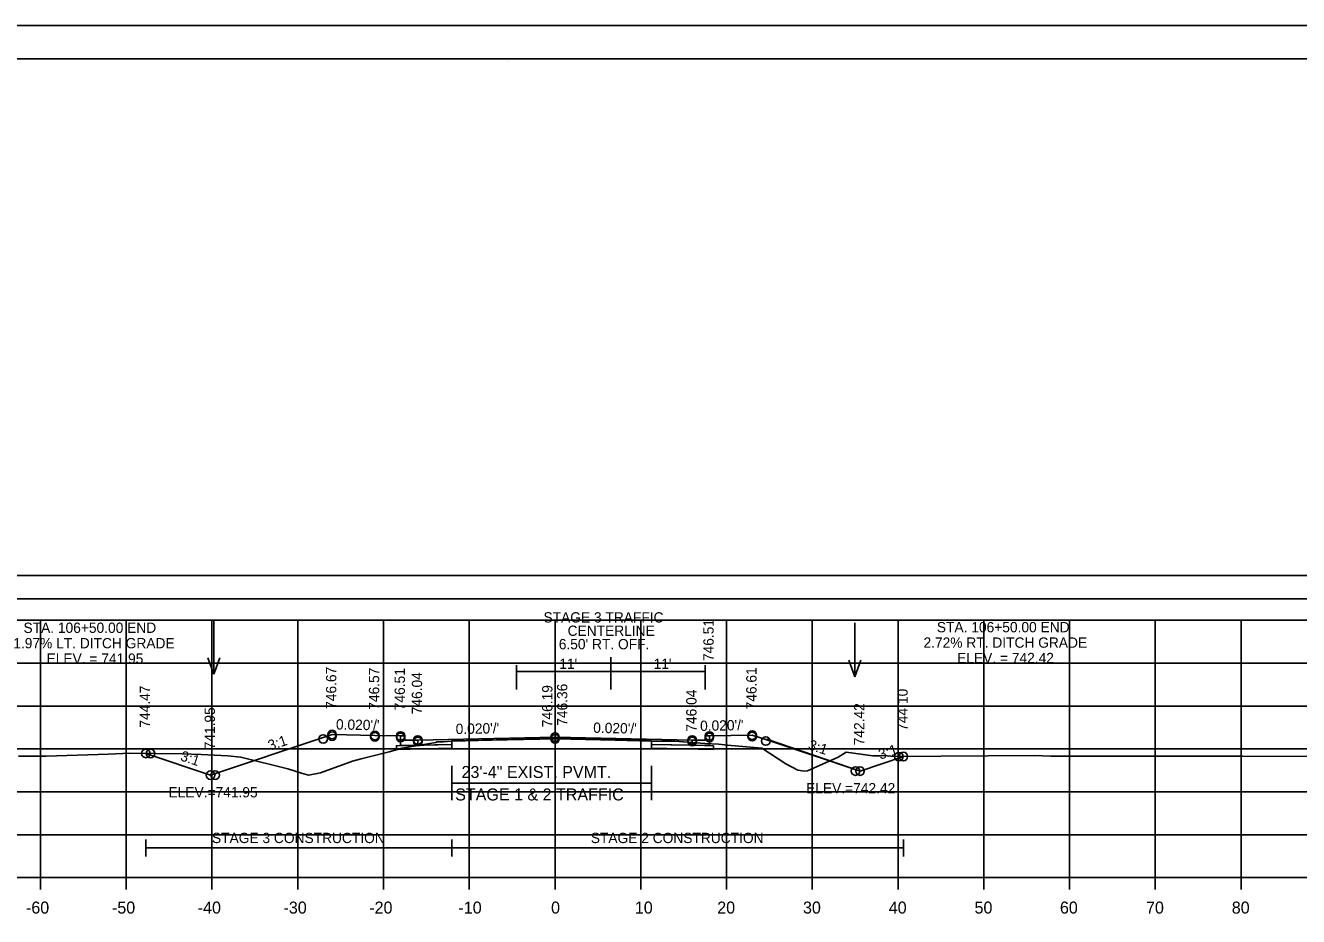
# Model space of a CAD drawing. Extents: x 1202951 to 1376887, y 378065 to 728038.
# Drawn here: x 1376522.9 to 1376671.4, y 379797.3 to 379901.2 of the extents above; entities that cross this region are included whole.
import ezdxf

# ---------------------------------------------------------------- set-up
doc = ezdxf.new("R2010")
doc.units = 0
for name, color, linetype in [('Default', 7, 'Continuous'), ('R_Alt Surface', 7, 'Continuous'), ('R_Axis', 7, 'Continuous'), ('R_Axis Annot', 7, 'Continuous'), ('R_Border', 7, 'Continuous'), ('R_Border Notes', 7, 'Continuous'), ('R_Dimension', 7, 'Continuous'), ('R_Exist Surface', 7, 'Continuous'), ('R_Fin Surface', 7, 'Continuous'), ('R_Grid', 7, 'Continuous'), ('R_MOT', 7, 'Continuous'), ('R_No Plot', 7, 'Continuous'), ('R_Proposed Const Limits', 7, 'Continuous'), ('R_Water Annot', 7, 'Continuous'), ('R_Xsect Elev', 7, 'Continuous'), ('R_Xsect Slope', 7, 'Continuous')]:
    doc.layers.add(name, color=color, linetype=linetype)

msp = doc.modelspace()

# ---------------------------------------------------------------- linework, layer by layer
at = {"layer": 'Default'}
for points in [[(1376558.67, 379818.51), (1376557.64, 379818.17), (1376557.64, 379818.17), (1376544.51, 379813.79)], [(1376607.67, 379818.45), (1376609.25, 379817.93), (1376609.25, 379817.93), (1376620.24, 379814.26)]]:
    msp.add_lwpolyline(points, dxfattribs=at)
for points in [[(1376566.67, 379818.35), (1376567.16, 379818.35), (1376567.17, 379817.85), (1376568.67, 379817.88), (1376568.67, 379817.26), (1376566.67, 379817.22)], [(1376602.67, 379818.35), (1376602.18, 379818.35), (1376602.17, 379817.85), (1376600.67, 379817.88), (1376600.67, 379817.26), (1376602.67, 379817.22)]]:
    msp.add_lwpolyline(points, close=True, dxfattribs=at)
at = {"layer": 'R_Alt Surface'}
for p, q in [((1376572.63, 379817.34), (1376566.17, 379817.21)), ((1376595.92, 379817.35), (1376602.67, 379817.22))]:
    msp.add_line(p, q, dxfattribs=at)
for points in [[(1376434.67, 379834.34), (1376710.2, 379834.34), (1376710.2, 379837.05), (1376434.67, 379837.05)], [(1376568.67, 379817.26), (1376567.17, 379817.23), (1376566.17, 379817.21), (1376566.17, 379816.79), (1376572.63, 379816.92), (1376572.63, 379817.34)], [(1376568.67, 379817.88), (1376568.67, 379817.26), (1376572.63, 379817.34), (1376572.63, 379817.8), (1376584.67, 379818.04), (1376595.92, 379817.81), (1376595.92, 379817.35), (1376600.67, 379817.26), (1376600.67, 379817.88), (1376600.67, 379817.88), (1376584.67, 379818.2), (1376568.67, 379817.88)], [(1376603.17, 379817.21), (1376602.1, 379817.23), (1376600.67, 379817.26), (1376595.92, 379817.35), (1376595.92, 379816.93), (1376603.17, 379816.79)]]:
    msp.add_lwpolyline(points, close=True, dxfattribs=at)
msp.add_lwpolyline([(1376566.67, 379818.35), (1376566.67, 379817.22), (1376568.67, 379817.26), (1376572.63, 379817.34), (1376572.63, 379817.8), (1376584.67, 379818.04), (1376595.92, 379817.81), (1376595.92, 379817.35), (1376600.67, 379817.26), (1376602.67, 379817.22), (1376602.67, 379818.35)], dxfattribs=at)
at = {"layer": 'R_Axis'}
for p, q in [((1376434.67, 379801.84), (1376734.67, 379801.84)), ((1376524.67, 379800.44), (1376524.67, 379801.84)), ((1376534.67, 379800.44), (1376534.67, 379801.84)), ((1376544.67, 379800.44), (1376544.67, 379801.84)), ((1376554.67, 379800.44), (1376554.67, 379801.84)), ((1376564.67, 379800.44), (1376564.67, 379801.84)), ((1376574.67, 379800.44), (1376574.67, 379801.84)), ((1376584.67, 379800.44), (1376584.67, 379801.84)), ((1376594.67, 379800.44), (1376594.67, 379801.84)), ((1376604.67, 379800.44), (1376604.67, 379801.84)), ((1376614.67, 379800.44), (1376614.67, 379801.84)), ((1376624.67, 379800.44), (1376624.67, 379801.84)), ((1376634.67, 379800.44), (1376634.67, 379801.84)), ((1376644.67, 379800.44), (1376644.67, 379801.84)), ((1376654.67, 379800.44), (1376654.67, 379801.84)), ((1376664.67, 379800.44), (1376664.67, 379801.84))]:
    msp.add_line(p, q, dxfattribs=at)
at = {"layer": 'R_Border'}
for p, q in [((1376426.67, 379897.3), (1376742.85, 379897.3)), ((1376579.19, 379897.04), (1376579.19, 379897.04)), ((1376579.19, 379897.04), (1376579.19, 379897.04))]:
    msp.add_line(p, q, dxfattribs=at)
at = {"layer": 'R_Dimension'}
for points in [[(1376536.95, 379806.29), (1376536.95, 379804.29)], [(1376536.95, 379805.29), (1376572.63, 379805.29)], [(1376572.63, 379806.29), (1376572.63, 379804.29)], [(1376572.63, 379805.29), (1376625.29, 379805.29)], [(1376625.29, 379806.29), (1376625.29, 379804.29)]]:
    msp.add_lwpolyline(points, dxfattribs=at)
at = {"layer": 'R_Exist Surface'}
msp.add_lwpolyline([(1376522.1, 379815.98), (1376522.99, 379815.98), (1376525.35, 379816.01), (1376532.6, 379816.24), (1376535.09, 379816.34), (1376541.19, 379816.26), (1376543.4, 379816.18), (1376546.52, 379816.03), (1376548.04, 379815.88), (1376553.5, 379814.51), (1376555.11, 379814), (1376555.94, 379813.79), (1376557.31, 379814.04), (1376561.04, 379815.43), (1376562.06, 379815.69), (1376565.35, 379816.5), (1376566.84, 379816.93), (1376569.15, 379817.33), (1376570.78, 379817.6), (1376570.89, 379817.65), (1376571.66, 379817.66), (1376572.63, 379817.75), (1376577.26, 379817.85), (1376584.77, 379818.03), (1376591.67, 379817.85), (1376595.92, 379817.76), (1376596.82, 379817.73), (1376598.64, 379817.73), (1376602.15, 379817.49), (1376603.73, 379817.38), (1376604.8, 379817.28), (1376608.78, 379816.93), (1376611.6, 379815.1), (1376612.97, 379814.35), (1376613.78, 379814.26), (1376614.12, 379814.29), (1376617.7, 379815.86), (1376618.61, 379816.45), (1376621.72, 379816.03), (1376622.58, 379816.04), (1376623.02, 379816.07), (1376624.23, 379815.94), (1376640.57, 379816.06), (1376641.53, 379816.03), (1376642.48, 379816.01), (1376661.53, 379816), (1376661.67, 379816), (1376664.85, 379816), (1376680.87, 379815.96)], dxfattribs=at)
at = {"layer": 'R_Fin Surface'}
for p, q in [((1376572.63, 379814.85), (1376572.63, 379810.85)), ((1376595.92, 379814.85), (1376595.92, 379810.85)), ((1376572.63, 379812.85), (1376595.92, 379812.85))]:
    msp.add_line(p, q, dxfattribs=at)
for points in [[(1376536.95, 379816.32), (1376544.51, 379813.79), (1376557.64, 379818.17), (1376558.67, 379818.51), (1376563.67, 379818.41), (1376566.67, 379818.35), (1376567.16, 379818.35), (1376567.17, 379817.85), (1376568.67, 379817.88), (1376584.67, 379818.2), (1376600.67, 379817.88), (1376602.17, 379817.85), (1376602.18, 379818.35), (1376602.67, 379818.35), (1376607.67, 379818.45), (1376609.25, 379817.93), (1376609.5, 379817.93), (1376620.24, 379814.26), (1376625.29, 379815.95)], [(1376558.67, 379818.51), (1376563.67, 379818.41), (1376566.67, 379818.35), (1376567.16, 379818.35), (1376567.17, 379817.85), (1376568.67, 379817.88), (1376568.67, 379817.88), (1376584.67, 379818.2), (1376600.67, 379817.88), (1376600.67, 379817.88), (1376602.17, 379817.85), (1376602.18, 379818.35), (1376602.67, 379818.35), (1376602.67, 379818.35), (1376607.67, 379818.45)]]:
    msp.add_lwpolyline(points, dxfattribs=at)
at = {"layer": 'R_Grid'}
for p, q in [((1376434.67, 379831.84), (1376734.67, 379831.84)), ((1376524.67, 379801.84), (1376524.67, 379831.84)), ((1376534.67, 379801.84), (1376534.67, 379831.84)), ((1376544.67, 379801.84), (1376544.67, 379831.84)), ((1376554.67, 379801.84), (1376554.67, 379831.84)), ((1376564.67, 379801.84), (1376564.67, 379831.84)), ((1376574.67, 379801.84), (1376574.67, 379831.84)), ((1376584.67, 379801.84), (1376584.67, 379831.84)), ((1376594.67, 379801.84), (1376594.67, 379831.84)), ((1376604.67, 379801.84), (1376604.67, 379831.84)), ((1376614.67, 379801.84), (1376614.67, 379831.84)), ((1376624.67, 379801.84), (1376624.67, 379831.84)), ((1376634.67, 379801.84), (1376634.67, 379831.84)), ((1376644.67, 379801.84), (1376644.67, 379831.84)), ((1376654.67, 379801.84), (1376654.67, 379831.84)), ((1376664.67, 379801.84), (1376664.67, 379831.84)), ((1376434.67, 379826.84), (1376734.67, 379826.84)), ((1376434.67, 379821.84), (1376734.67, 379821.84)), ((1376434.67, 379816.84), (1376734.67, 379816.84)), ((1376434.67, 379811.84), (1376734.67, 379811.84)), ((1376434.67, 379806.84), (1376734.67, 379806.84)), ((1376434.67, 379801.84), (1376734.67, 379801.84))]:
    msp.add_line(p, q, dxfattribs=at)
at = {"layer": 'R_MOT'}
for p, q in [((1376591.18, 379827.53), (1376591.18, 379823.77)), ((1376580.18, 379826.62), (1376580.18, 379823.77)), ((1376580.18, 379825.87), (1376591.18, 379825.87)), ((1376591.18, 379825.87), (1376602.18, 379825.87)), ((1376602.18, 379826.62), (1376602.18, 379823.77))]:
    msp.add_line(p, q, dxfattribs=at)
at = {"layer": 'R_No Plot'}
msp.add_line((1376414.27, 379901.2), (1376747.6, 379901.2), dxfattribs=at)
for points in [[(1376414.27, 380114.54), (1376747.61, 380114.54), (1376747.61, 379901.2), (1376414.27, 379901.2)], [(1376414.26, 379901.2), (1376747.6, 379901.2), (1376747.6, 379687.86), (1376414.26, 379687.86)], [(1376660.59, 379897.3), (1376680.21, 379897.3), (1376680.21, 379887.42), (1376696.32, 379887.42), (1376719.52, 379887.42), (1376719.64, 379859.27), (1376742.85, 379859.27), (1376742.85, 379691.84), (1376426.67, 379691.84), (1376426.67, 379897.3)]]:
    msp.add_lwpolyline(points, close=True, dxfattribs=at)
for centre in [(1376557.64, 379818), (1376558.67, 379818.51), (1376558.67, 379818.34), (1376563.67, 379818.41), (1376563.67, 379818.24), (1376566.67, 379818.35), (1376566.67, 379818.18), (1376568.67, 379817.88), (1376584.67, 379818.2), (1376584.67, 379818.03), (1376600.67, 379817.88), (1376602.67, 379818.35), (1376602.67, 379818.35), (1376602.67, 379818.18), (1376602.67, 379818.18), (1376607.67, 379818.45), (1376607.67, 379818.28), (1376609.25, 379817.76), (1376536.95, 379816.32), (1376537.49, 379816.31), (1376568.67, 379817.71), (1376600.67, 379817.71), (1376624.76, 379815.94), (1376625.29, 379815.95), (1376544.51, 379813.79), (1376545.03, 379813.79), (1376619.72, 379814.26), (1376620.24, 379814.26)]:
    msp.add_circle(centre, 0.5, dxfattribs=at)
at = {"layer": 'R_Proposed Const Limits'}
for points in [[(1376544.51, 379813.79), (1376536.95, 379816.32)], [(1376620.24, 379814.26), (1376625.29, 379815.95)]]:
    msp.add_lwpolyline(points, dxfattribs=at)
at = {"layer": 'R_Water Annot'}
for p, q in [((1376544.87, 379831.83), (1376544.87, 379825.54)), ((1376619.64, 379831.54), (1376619.64, 379825.26)), ((1376544.87, 379825.54), (1376544.17, 379827.47)), ((1376544.87, 379825.54), (1376545.57, 379827.47)), ((1376619.64, 379825.26), (1376618.94, 379827.18)), ((1376619.64, 379825.26), (1376620.34, 379827.18))]:
    msp.add_line(p, q, dxfattribs=at)
at = {"layer": 'R_Xsect Elev'}
msp.add_line((1376584.67, 379818.03), (1376584.67, 379825.39), dxfattribs=at)

# ---------------------------------------------------------------- texts
at = {"layer": 'R_Axis Annot'}
for s, p in [('23\'-4" EXIST. PVMT.', (1376573.77, 379813.45)), ('STAGE 1 & 2 TRAFFIC', (1376573.03, 379810.83)), ('-60', (1376522.98, 379797.64)), ('-50', (1376533.01, 379797.64)), ('-40', (1376543.01, 379797.64)), ('-30', (1376553.01, 379797.64)), ('-20', (1376563.01, 379797.64)), ('-10', (1376573.41, 379797.64)), ('0', (1376584.21, 379797.64)), ('10', (1376593.98, 379797.64)), ('20', (1376603.59, 379797.64)), ('30', (1376613.59, 379797.64)), ('40', (1376623.59, 379797.64)), ('50', (1376633.59, 379797.64)), ('60', (1376643.55, 379797.64)), ('70', (1376653.59, 379797.64)), ('80', (1376663.59, 379797.64))]:
    msp.add_text(s, height=1.4, dxfattribs=at).set_placement(p)
at = {"layer": 'R_Border Notes'}
for s, p in [('STA. 106+50.00 END ', (1376629.2, 379830.44)), ('STA. 106+50.00 END', (1376522.69, 379830.37)), ('1.97% LT. DITCH GRADE ', (1376521.5, 379828.57)), ('2.72% RT. DITCH GRADE', (1376627.64, 379828.64)), ('ELEV. = 741.95', (1376525.38, 379826.77)), ('ELEV. = 742.42', (1376631.56, 379826.84)), ('ELEV.=741.95', (1376539.6, 379811.19)), ('ELEV.=742.42', (1376613.95, 379811.66))]:
    msp.add_text(s, height=1.2, dxfattribs=at).set_placement(p)
at = {"layer": 'R_Dimension'}
for s, p in [('STAGE 3 CONSTRUCTION', (1376544.67, 379805.86)), ('STAGE 2 CONSTRUCTION', (1376588.84, 379805.86))]:
    msp.add_text(s, height=1.2, dxfattribs=at).set_placement(p)
at = {"layer": 'R_MOT'}
for s, p in [('STAGE 3 TRAFFIC ', (1376583.33, 379831.58)), ('CENTERLINE', (1376586.14, 379830.02)), ("6.50' RT. OFF.", (1376585.11, 379828.46)), ("11'", (1376585.17, 379826.17)), ("11'", (1376596.17, 379826.17))]:
    msp.add_text(s, height=1.2, dxfattribs=at).set_placement(p)
at = {"layer": 'R_Xsect Elev'}
for s, p in [('746.51', (1376603.17, 379827.08)), ('746.67', (1376559.17, 379821.51)), ('746.57', (1376564.17, 379821.41)), ('746.51', (1376567.17, 379821.35)), ('746.04', (1376569.17, 379820.88)), ('746.61', (1376608.17, 379821.45)), ('746.19', (1376584.37, 379819.37)), ('746.36', (1376586.11, 379819.54)), ('744.47', (1376537.45, 379819.32)), ('746.04', (1376601.17, 379818.85)), ('744.10', (1376625.79, 379818.95)), ('741.95', (1376545.01, 379816.79)), ('742.42', (1376620.74, 379817.26))]:
    msp.add_text(s, height=1.2, rotation=90, dxfattribs=at).set_placement(p)
at = {"layer": 'R_Xsect Slope'}
for s, rotation, p in [("0.020'/'", 358.8542, (1376559.12, 379819.11)), ("0.020'/'", 1.1458, (1376573.1, 379818.57)), ("0.020'/'", 358.8542, (1376589.12, 379818.72)), ("0.020'/'", 1.1458, (1376601.6, 379818.93)), ('3:1', 18.4349, (1376551.43, 379816.63)), ('3:1', 341.5651, (1376614.11, 379816.83)), ('3:1', 18.4349, (1376622.61, 379815.58)), ('3:1', 341.5651, (1376540.89, 379815.53))]:
    msp.add_text(s, height=1.2, rotation=rotation, dxfattribs=at).set_placement(p)

doc.saveas('drawing.dxf')
